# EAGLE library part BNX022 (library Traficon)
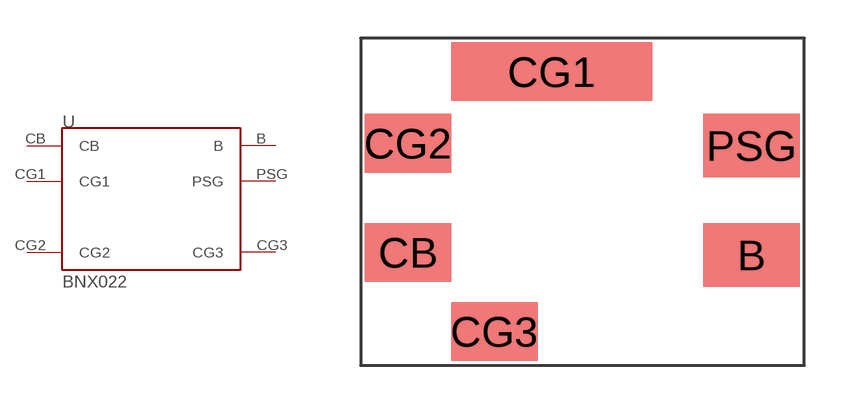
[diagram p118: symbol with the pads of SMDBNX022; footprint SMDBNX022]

Designator prefix U

## BNX022  [SMDBNX022]
B  B
CB  CB
CG1  CG1
CG2  CG2
CG3  CG3
PSG  PSG

## Footprint SMDBNX022 (pad centres in mm)
smd 3.8 x 2.5: B -1.901,-8.35; PSG -1.901,-4.05
smd 3.4 x 2.3: CB -15.383,-8.246; CG2 -15.388,-3.961; CG3 -11.991,-11.35
smd 7.9 x 2.3: CG1 -9.75,-1.15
